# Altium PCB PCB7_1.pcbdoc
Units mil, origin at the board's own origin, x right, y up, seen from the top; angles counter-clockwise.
Board outline 1240 x 2672.95 mil, 2 copper layers (Top Layer, Bottom Layer); 61 components, 30 nets, 228 pads, 88 vias.
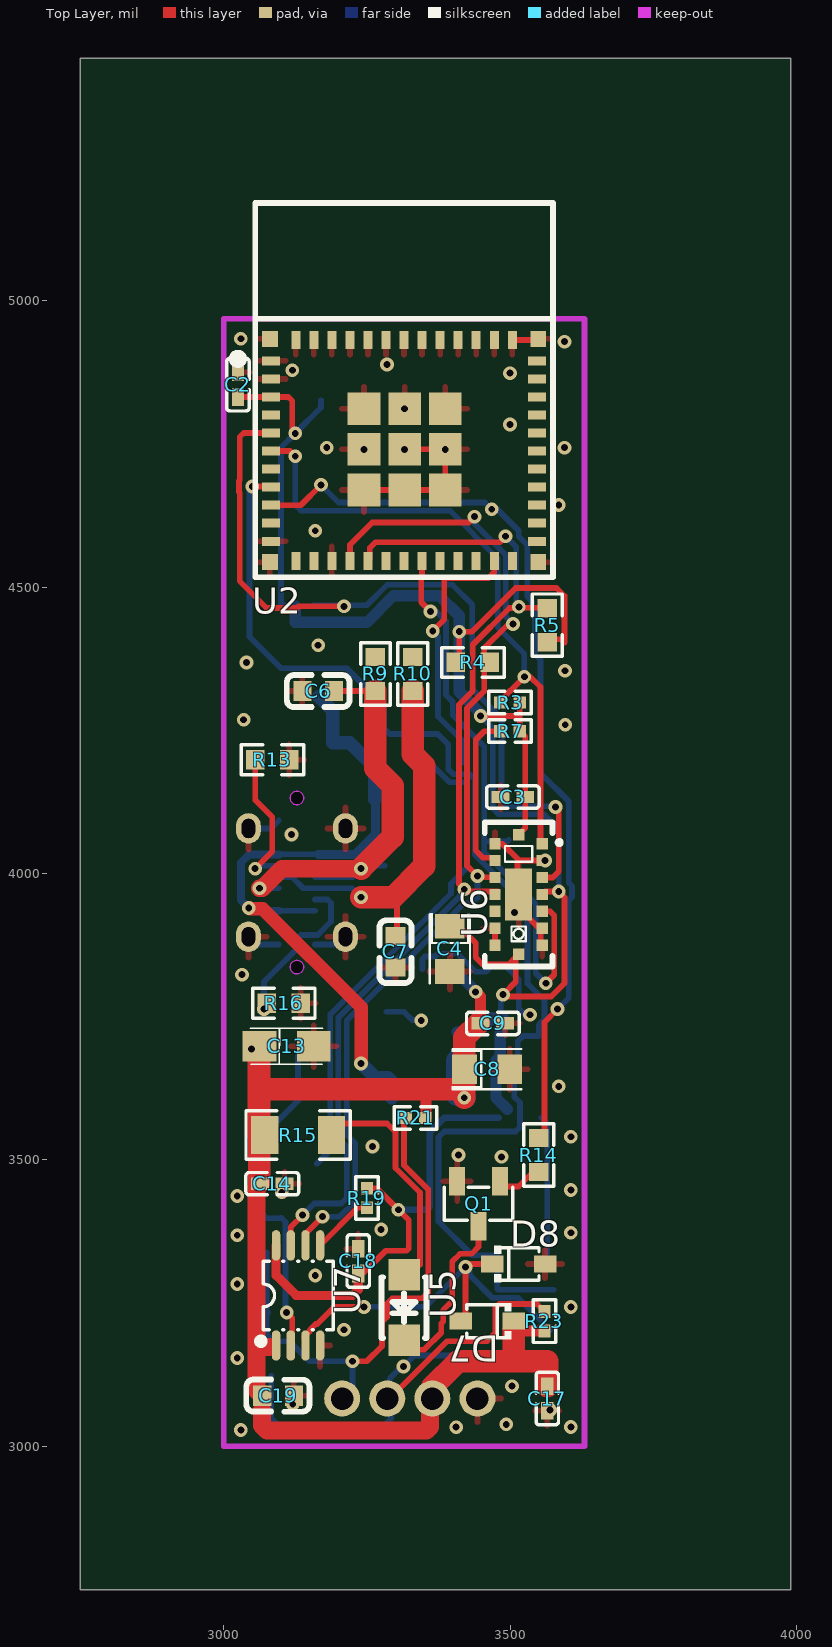
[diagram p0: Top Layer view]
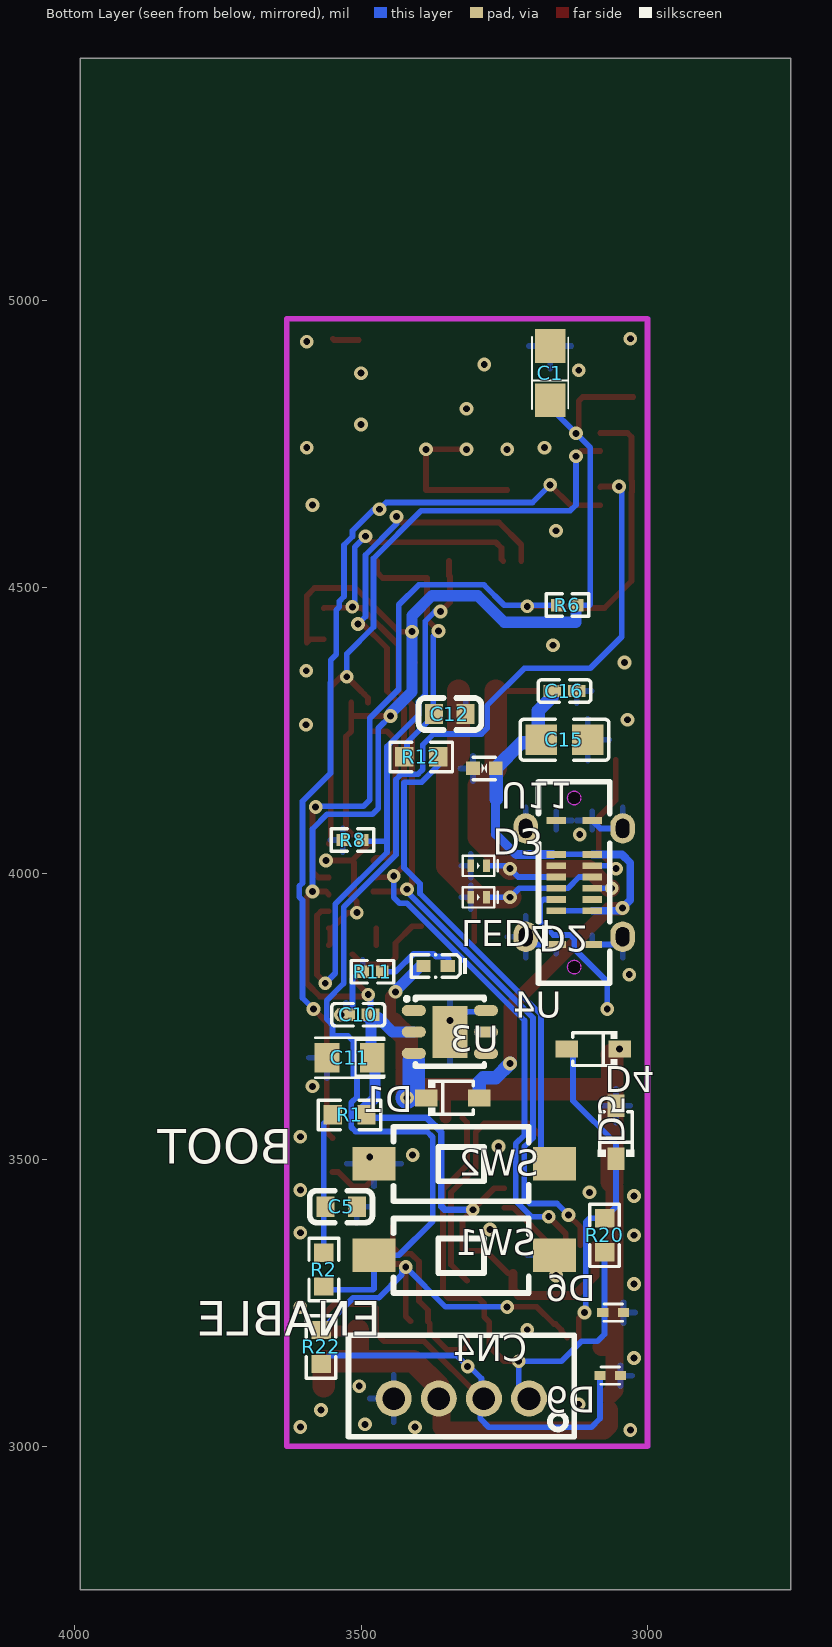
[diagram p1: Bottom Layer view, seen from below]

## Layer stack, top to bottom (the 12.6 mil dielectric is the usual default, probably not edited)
Top Layer: signal copper (thickness not stored)
Dielectric: dielectric 12.6, FR-4, Dk 4.8
Bottom Layer: signal copper (thickness not stored)

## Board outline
3990,2750 2750,2750 2750,5422.95 3990,5422.95

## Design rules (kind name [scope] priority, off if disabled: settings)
BoardOutlineClearance copperThickness1oz [All] p0: genericclearance=10 ignorepadtopadclearanceinfootprint=FALSE except(0: Arc-SplitContinuation Track-SplitContinuation SMDPad-SplitContinuation THPad-SplitContinuation Via-SplitContinuation Fill-SplitContinuation Poly-SplitContinuation Region-SplitContinuation Text-SplitContinuation; 6: Track-CutoutEdge SMDPad-CutoutEdge THPad-CutoutEdge Via-CutoutEdge Region-CutoutEdge; 11.8: Track-OutlineEdge SMDPad-OutlineEdge THPad-OutlineEdge Via-OutlineEdge Fill-OutlineEdge Region-OutlineEdge Poly-OutlineEdge Text-OutlineEdge Fill-CutoutEdge)
BoardOutlineClearance copperThickness2oz [All] p0: genericclearance=10 ignorepadtopadclearanceinfootprint=FALSE except(0: Arc-SplitContinuation Track-SplitContinuation SMDPad-SplitContinuation THPad-SplitContinuation Via-SplitContinuation Fill-SplitContinuation Poly-SplitContinuation Region-SplitContinuation Text-SplitContinuation; 6: Track-CutoutEdge SMDPad-CutoutEdge THPad-CutoutEdge Via-CutoutEdge Region-CutoutEdge; 11.8: Track-OutlineEdge SMDPad-OutlineEdge THPad-OutlineEdge Via-OutlineEdge Fill-OutlineEdge Region-OutlineEdge Poly-OutlineEdge Text-OutlineEdge Fill-CutoutEdge)
Clearance copperThickness1oz [(InNet('VDD33') OR InNet('GND') OR InNet('$3N26046') OR InNet('GPIO12_USB_DN') OR InNet('GPIO13_USB_DP') OR InNet('+5V_USB') OR InNet('$3N7934') OR InNet('$3N11377') OR InNet('$3N11381') OR InNet('GPIO2') OR InNet('GPIO3') OR InNet('I2C_SDA') OR InNet('I2C_SCL') OR InNet('ENABLE') OR InNet('$3N7054') OR InNet('$3N7060') OR InNet('$3N26307') OR InNet('GPIO4') OR InNet('$3N11357') OR InNet('$3N17354') OR InNet('GPIO14') OR InNet('$3N33566') OR InNet('$4N496') OR InNet('SCL1_S5V') OR InNet('SDA1_S5V') OR InNet('VBUS') OR InNet('SCL1_A5V') OR InNet('$3N36981') OR InNet('SDA1_A5V') OR InNet('$3N35247'))] p1: gap=7 ignorepadtopadclearanceinfootprint=FALSE except(4: Track-Track; 6: Track-SMDPad SMDPad-SMDPad Track-THPad SMDPad-THPad THPad-THPad Track-Via SMDPad-Via THPad-Via Via-Via SMDPad-Fill THPad-Fill Via-Fill Fill-Fill Track-Region SMDPad-Region THPad-Region Via-Region Region-Region Track-Poly SMDPad-Poly THPad-Poly Via-Poly Fill-Poly Region-Poly Poly-Poly Track-Text SMDPad-Text THPad-Text Via-Text Fill-Text Region-Text Poly-Text Text-Text; 6.9: Track-Hole SMDPad-Hole THPad-Hole Via-Hole Fill-Hole Region-Hole Poly-Hole Text-Hole Sheet-Hole; 11.8: Track-Fill Fill-Region Track-Sheet SMDPad-Sheet THPad-Sheet Via-Sheet Fill-Sheet Region-Sheet Poly-Sheet Text-Sheet)
Clearance copperThickness2oz [All] p1: gap=7 ignorepadtopadclearanceinfootprint=FALSE except(6: Track-SMDPad SMDPad-SMDPad Track-THPad SMDPad-THPad THPad-THPad Track-Via SMDPad-Via THPad-Via Via-Via SMDPad-Fill THPad-Fill Via-Fill Fill-Fill Track-Region SMDPad-Region THPad-Region Via-Region Region-Region Track-Poly SMDPad-Poly THPad-Poly Via-Poly Fill-Poly Region-Poly Poly-Poly Track-Text SMDPad-Text THPad-Text Via-Text Fill-Text Region-Text Poly-Text Text-Text; 6.9: Track-Hole SMDPad-Hole THPad-Hole Via-Hole Fill-Hole Region-Hole Poly-Hole Text-Hole Sheet-Hole; 8: Track-Track; 11.8: Track-Fill Fill-Region Track-Sheet SMDPad-Sheet THPad-Sheet Via-Sheet Fill-Sheet Region-Sheet Poly-Sheet Text-Sheet)
DiffPairsRouting differentialPair [All] p1: maxuncoupledlength=10 minlimit=5.9843 maxlimit=5.9843 mostfreqgap=5.9843 toplayer_minwidth=5 toplayer_prefwidth=10 toplayer_maxwidth=100 bottomlayer_minwidth=5 bottomlayer_prefwidth=10 bottomlayer_maxwidth=100
PasteMaskExpansion pasteMaskExpansion [All] p1: expansion=0
PlaneConnect innerPlane [All] p1: planeconnectstyle=Relief reliefexpansion=20 reliefentries=4 reliefconductorwidth=10 reliefairgap=10
PolygonConnect copperRegion [All] p1: connectstyle=Direct reliefentries=4 reliefconductorwidth=10 polygonreliefangle="90 Angle" airgapwidth=10
PolygonConnect USB_CR [All] p1: connectstyle=Direct reliefentries=4 reliefconductorwidth=10 polygonreliefangle="90 Angle" airgapwidth=10
PolygonConnect GND [All] p1: connectstyle=Relief reliefentries=4 reliefconductorwidth=10 polygonreliefangle="90 Angle" airgapwidth=10
RoutingVias viaSize [All] p1: viastyle="Through Hole" holewidth=12.0078 minholewidth=11.811 maxholewidth=248.0314 width=24.0158 minwidth=19.685 maxwidth=393.7008
SolderMaskExpansion solderMaskExpansion [All] p1: useseparateexpansions=TRUE expansion=2.0079 expansionbottom=2.0079
Width copperThickness1oz [All] p1: maxlimit=100 minlimit=5 preferedwidth=10
Width copperThickness2oz [All] p1: maxlimit=100 minlimit=8 preferedwidth=10

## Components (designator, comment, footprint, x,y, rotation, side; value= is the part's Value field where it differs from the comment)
C1 "" CASE-A_3216 3170,4873.5 r90 bottom
C2 "" C0402 3025,4853.5 r270 top locked
C3 "" C0402 3505,4133.5 r180 top
C4 "" CAP-SMD_L2.0-W1.3-FD 3395,3868.5 r270 top
C5 "" C0603 3535,3418.5 r180 bottom
C6 "" C0603 3165,4318.5 r180 top
C7 "" C0603 3300,3863.5 r270 top
C8 "" CAP-SMD_L2.0-W1.3-FD 3460,3658.5 r0 top
C9 "" C0402 3470,3738.5 r0 top
C10 "" C0402 3505,3753.5 r0 bottom
C11 "" CAP-SMD_L2.0-W1.3-FD 3520,3678.5 r0 bottom
C12 "" C0603 3345,4278.5 r180 bottom
C13 "" CASE-A_3216 3110,3698.5 r0 top
C14 "" C0402 3085,3458.5 r180 top
C15 "" C0805 3145,4233.5 r180 bottom
C16 "" C0402 3145,4318.5 r180 bottom
C17 "" C0402 3565,3083.5 r270 top
C18 "" C0402 3235,3323.5 r270 top
C19 "" C0603 3095,3088.5 r0 top
CN4 "" CONN-TH_B4B-PH-K-S 3325,3083.5 r180 bottom locked
D1 "" SOD-323_L1.8-W1.3-LS2.5-RD 3340,3608.5 r180 bottom
D2 "" X2SON-2_L1.0-W0.6-P0.70-RD 3295,3958.5 r0 bottom
D3 "" X2SON-2_L1.0-W0.6-P0.70-RD 3295,4013.5 r0 bottom
D4 "" SOD-323_L1.8-W1.3-LS2.5-RD 3095,3693.5 r0 bottom
D5 "" SOD-323_L1.8-W1.3-LS2.5-RD 3055,3548.5 r90 bottom
D6 "" SOD-923_L0.8-W0.6-LS1.0-BI 3060,3233.5 r180 bottom
D7 "" SOD-323_L1.8-W1.3-LS2.5-RD 3460,3218.5 r180 top
D8 "" SOD-323_L1.8-W1.3-LS2.5-RD 3515,3318.5 r0 top
D9 "" SOD-923_L0.8-W0.6-LS1.0-BI 3065,3123.5 r180 bottom
LED4 "" LED0402-RD_BLUE 3370,3838.5 r0 bottom
Q1 "" SOT-23-3_L2.9-W1.3-P1.90-LS2.4-BR 3445,3423.5 r90 top
R1 "" R0603 3520,3578.5 r180 bottom
R2 "" R0603 3565,3308.5 r270 bottom
R3 "" R0402 3500,4298.5 r0 top
R4 "" R0603 3435,4368.5 r180 top
R5 "" R0603 3565,4433.5 r270 top
R6 "" R0402 3140,4468.5 r180 bottom
R7 "" R0402 3500,4248.5 r0 top
R8 "" R0402 3515,4058.5 r180 bottom
R9 "" R0603 3265,4348.5 r90 top
R10 "" R0603 3330,4348.5 r90 top
R11 "" R0402 3480,3828.5 r0 bottom
R12 "" R0603 3395,4203.5 r0 bottom
R13 "" R0603 3085,4198.5 r0 top
R14 "" R0603 3550,3508.5 r270 top
R15 "" R1206 3130,3543.5 r0 top
R16 "" R0603 3105,3773.5 r0 top
R19 "" R0402 3250,3433.5 r270 top
R20 "" R0603 3075,3368.5 r270 bottom
R21 "" R0402 3335,3573.5 r0 top
R22 "" R0603 3570,3173.5 r270 bottom
R23 "" R0402 3560,3218.5 r270 top
SW1 "" SW-SMD_L6.0-W3.3-LS8.0 3320,3333.5 r180 bottom locked
SW2 "" SW-SMD_L6.0-W3.3-LS8.0 3320,3493.5 r180 bottom locked
U2 "" WIFIM-SMD_61P-L16.6-W13.2-P0.80-ESP32-C6-MINI-1-N4 3314.96,4738.5 r0 top locked
U3 "" DFN-6_L3.0-W3.0-P0.95-BL-EP-1 3345,3723.5 r270 bottom
U4 "" TYPE-C-SMD_USB4120-03-C 3127.95,3984.25 r90 bottom locked
U5 "" LED-SMD_L3.0-W2.0-R-RD 3314.96,3242.17 r90 top
U6 "" LGA-16_L6.4-W3.0_VL53L5CXV0GC-1 3515,3963.5 r90 top
U7 "" TSSOP-8_L3.0-W3.0-P0.65-LS4.9-BL 3130,3263.5 r0 top
U11 "" X1SON-2_L1.0-W0.6-P0.65-BI 3285,4183.5 r0 bottom

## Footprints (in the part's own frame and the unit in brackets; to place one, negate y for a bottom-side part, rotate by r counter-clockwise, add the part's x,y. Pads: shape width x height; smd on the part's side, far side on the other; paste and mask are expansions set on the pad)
C0402 [mm]
  rect 0.79x0.54 smd: 1(-0.545,0) 2(0.545,0)
  silkscreen extent -1.17,-0.5 1.17,0.5
C0603 [mm]
  rect 0.8x0.9 smd: 1(-0.7,0) 2(0.7,0)
  silkscreen extent -1.39,-0.71 1.39,0.71
C0805 [mm]
  rect 1.41x1.35 smd: 1(-1.03,0) 2(1.03,0)
  silkscreen extent -1.96,-0.9 1.96,0.9
CAP-SMD_L2.0-W1.3-FD [mm]
  rect 1.1x1.3 smd: 1(-1,0) 2(1,0)
  silkscreen extent -1.57,-0.89 1.52,0.89
CASE-A_3216 [mil]
  rect 59.05x53.5 smd: 1(-47.24,0) 2(47.24,0)
  silkscreen extent -63,-32 63,32
CONN-TH_B4B-PH-K-S [mm]
  round 1.6 hole 1: 1(3,0) 2(1,0) 3(-1,0) 4(-3,0)
  silkscreen extent -5,-1.7 5,2.8
DFN-6_L3.0-W3.0-P0.95-BL-EP-1 [mm]
  oval 0.49x1.07 smd: 1(-0.95,-1.6) 2(0,-1.6) 3(0.95,-1.6) 4(0.95,1.6) 5(0,1.6) 6(-0.95,1.6)
  rect 2.3x1.55 smd: 7(0,0)
  silkscreen extent -1.56,-2 1.52,1.52
LED0402-RD_BLUE [mm]
  rect 0.636x0.54 smd: 1(-0.538,0) 2(0.538,0)
  silkscreen extent -1.39,-0.54 1.09,0.54
LED-SMD_L3.0-W2.0-R-RD [mm]
  rect 1.4x1.4 smd: 1(1.45,0) 2(-1.45,0)
  silkscreen extent -1.35,-1 1.35,1
LGA-16_L6.4-W3.0_VL53L5CXV0GC-1 [mm]
  rect 0.5x0.5 smd: A1(2.25,-1.05) A2(1.5,-1.05) A3(0.75,-1.05) A4(0,-1.05) A5(-0.75,-1.05) A6(-1.5,-1.05) A7(-2.25,-1.05) B1(2.65,0) B7(-2.65,0) C1(2.25,1.05) C2(1.5,1.05) C3(0.75,1.05) C4(0,1.05) C5(-0.75,1.05) C6(-1.5,1.05) C7(-2.25,1.05)
  rect 2.316x1.2 smd: B4(0,0)
  silkscreen extent -3.2,-1.9 3.2,1.5
R0402 [mm]
  rect 0.566x0.54 smd: 1(-0.433,0) 2(0.433,0)
  silkscreen extent -0.94,-0.5 0.94,0.5
R0603 [mil]
  rect 31.75x34.02 smd: 1(-29.66,0) 2(29.66,0)
  silkscreen extent -55,-26 55,26
R1206 [mil]
  rect 47.54x66.97 smd: 1(-58.22,0) 2(58.22,0)
  silkscreen extent -91,-42 91,42
SOD-323_L1.8-W1.3-LS2.5-RD [mm]
  rect 1x0.75 smd: 1(-1.173,0) 2(1.173,0)
  silkscreen extent -1.08,-0.8 0.9,0.8
SOD-923_L0.8-W0.6-LS1.0-BI [mm]
  rect 0.5x0.4 smd: 1(-0.457,0) 2(0.457,0)
  silkscreen extent -0.41,-0.38 0.41,0.38
SOT-23-3_L2.9-W1.3-P1.90-LS2.4-BR [mm]
  rect 1.25x0.7 smd: 1(1,-0.95) 2(1,0.95) 3(-1,0)
  silkscreen extent -0.73,-1.53 0.73,1.53
SW-SMD_L6.0-W3.3-LS8.0 [mm]
  rect 1.9x1.5 smd: 1(-4,0) 2(4,0)
  silkscreen extent -3.14,-1.67 2.86,1.63
TSSOP-8_L3.0-W3.0-P0.65-LS4.9-BL [mm]
  oval 0.37x1.35 smd: 1(-0.975,-2.22) 2(-0.325,-2.22) 3(0.325,-2.22) 4(0.975,-2.22) 5(0.975,2.22) 6(0.325,2.22) 7(-0.325,2.22) 8(-0.975,2.22)
  silkscreen extent -1.8,-2.18 1.55,1.52
TYPE-C-SMD_USB4120-03-C [mm]
  oval 1.35x1.1 hole 0.6 slot 0.85 at 0 deg: 0(-2.4,-2.15) 0(-2.4,2.15) 0(2.4,-2.15) 0(2.4,2.15)
  rect 0.3x0.87 smd: A1(-2.75,0.8) A4(-1.25,0.8) A5(-0.75,0.8) A6(-0.25,0.8) A7(0.25,0.8) A8(0.75,0.8) A9(1.25,0.8) A12(2.75,0.8) B1(2.75,-0.8) B4(1.25,-0.8) B5(0.75,-0.8) B6(0.25,-0.8) B7(-0.25,-0.8) B8(-0.75,-0.8) B9(-1.25,-0.8) B12(-2.75,-0.8)
  Board Outline Layer circle w0.005: c-3.75,0 r0.3
  Board Outline Layer circle w0.005: c3.75,0 r0.3
  Board Outline Layer region: -3.75,0.3 -3.88,0.27 -3.985,0.187 -4.043,0.067 -4.043,-0.067 -3.985,-0.187 -3.88,-0.27 -3.75,-0.3 -3.75,-0.3 -3.62,-0.27 -3.516,-0.187 -3.458,-0.067 -3.458,0.067 -3.516,0.187 -3.62,0.27 -3.75,0.3
  Board Outline Layer region: 3.75,0.3 3.62,0.27 3.516,0.187 3.458,0.067 3.458,-0.067 3.516,-0.187 3.62,-0.27 3.75,-0.3 3.75,-0.3 3.88,-0.27 3.985,-0.187 4.043,-0.067 4.043,0.067 3.985,0.187 3.88,0.27 3.75,0.3
  Multi-Layer board cut-out: -3.75,0.3 -3.88,0.27 -3.985,0.187 -4.043,0.067 -4.043,-0.067 -3.985,-0.187 -3.88,-0.27 -3.75,-0.3 -3.75,-0.3 -3.62,-0.27 -3.516,-0.187 -3.458,-0.067 -3.458,0.067 -3.516,0.187 -3.62,0.27 -3.75,0.3
  Multi-Layer board cut-out: 3.75,0.3 3.62,0.27 3.516,0.187 3.458,0.067 3.458,-0.067 3.516,-0.187 3.62,-0.27 3.75,-0.3 3.75,-0.3 3.88,-0.27 3.985,-0.187 4.043,-0.067 4.043,0.067 3.985,0.187 3.88,0.27 3.75,0.3
  silkscreen extent -4.47,-1.58 4.47,1.58
WIFIM-SMD_61P-L16.6-W13.2-P0.80-ESP32-C6-MINI-1-N4 [mm]
  rect 0.8x0.4 smd: 1(-5.9,3.975) 2(-5.9,3.175) 3(-5.9,2.375) 4(-5.9,1.575) 5(-5.9,0.775) 6(-5.9,-0.025) 7(-5.9,-0.825) 8(-5.9,-1.625) 9(-5.9,-2.425) 10(-5.9,-3.225) 11(-5.9,-4.025) 25(5.9,-4.025) 26(5.9,-3.225) 27(5.9,-2.425) 28(5.9,-1.625) 29(5.9,-0.825) 30(5.9,-0.025) 31(5.9,0.775) 32(5.9,1.575) 33(5.9,2.375) 34(5.9,3.175) 35(5.9,3.975)
  rect 0.4x0.8 smd: 12(-4.8,-4.9) 13(-4,-4.9) 14(-3.2,-4.9) 15(-2.4,-4.9) 16(-1.6,-4.9) 17(-0.8,-4.9) 18(0,-4.9) 19(0.8,-4.9) 20(1.6,-4.9) 21(2.4,-4.9) 22(3.2,-4.9) 23(4,-4.9) 24(4.8,-4.9) 36(4.8,4.9) 37(4,4.9) 38(3.2,4.9) 39(2.4,4.9) 40(1.6,4.9) 41(0.8,4.9) 42(0,4.9) 43(-0.8,4.9) 44(-1.6,4.9) 45(-2.4,4.9) 46(-3.2,4.9) 47(-4,4.9) 48(-4.8,4.9)
  rect 1.45x1.45 smd: 49(-1.775,-1.75) 49(-1.775,0.05) 49(-1.775,1.85) 49(0.025,-1.75) 49(0.025,0.05) 49(0.025,1.85) 49(1.825,-1.75) 49(1.825,0.05) 49(1.825,1.85)
  rect 0.7x0.7 smd: 50(5.95,4.95) 51(5.95,-4.95) 52(-5.95,-4.95) 53(-5.95,4.95)
  silkscreen extent -7.57,-5.62 6.6,10.98
X1SON-2_L1.0-W0.6-P0.65-BI [mm]
  rect 0.6x0.6 smd: 1(-0.5,0) 2(0.5,0)
  silkscreen extent -0.5,-0.5 0.5,0.5
X2SON-2_L1.0-W0.6-P0.70-RD [mm]
  rect 0.3x0.55 smd: 1(-0.35,0) 2(0.35,0)
  silkscreen extent -0.85,-0.45 0.7,0.45

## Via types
v1: diameter 24.02, hole 12.01, Top Layer to Bottom Layer, 88 vias

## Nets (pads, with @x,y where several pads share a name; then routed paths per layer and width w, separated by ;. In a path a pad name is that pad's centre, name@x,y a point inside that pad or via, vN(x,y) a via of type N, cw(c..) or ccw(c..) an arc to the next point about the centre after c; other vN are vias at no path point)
$3N7054: R9.2 U2.17
$3N7060: R10.2 U2.18
$3N7934: C12.1 R12.2 U2.23 | length 464.9
  Top Layer w10: v1(3365,4423.5) 3385,4443.5 3385,4515.95 3462.44,4515.95 3472.44,4525.95 U2.23
  Bottom Layer w10: v1(3365,4423.5) 3374.25,4414.25 3374.25,4274.25 3420,4228.5 3420,4193.84 R12.2@3419.66,4193.5
$3N11357: R15.2 U5.1 | length 415.1
  Top Layer w10: R15.2 3208.3,3563.58 3285,3563.58 3300,3548.58 3300,3486.02 3342.99,3443.03 3342.99,3317.29 U5.1@3314.96,3289.26
$3N11377: Q1.1 R14.2 | length 82
  Top Layer w10: Q1.1 3491.77,3453.5 3514.66,3453.5 3540,3478.84 R14.2
$3N11381: Q1.3 U5.2 | length 314.4
  Top Layer w10: U5.2 3314.96,3175.08 3321.53,3168.5 3350,3168.5 3380,3198.5 3380,3214.65 3383.17,3217.82 3383.17,3237.82 3399.09,3253.75 3399.09,3322.58 3412.56,3336.05 3432.55,3336.05 3445,3348.5 Q1.3
$3N17354: R16.1 U4.A5 | length 281.4
  Bottom Layer w10: v1(3070.34,3763.5) 3070.34,3811.24 3127.93,3868.83 3127.93,3885.8 3135,3892.87 3164.37,3892.87 3187.56,3916.06 3187.56,3948.5 3181.34,3954.72 U4.A5
$3N26046: C5.1 R1.1 R2.1 | length 239.8
  Bottom Layer w10: R1.1@3555,3573.84 3565,3563.84 R2.1
$3N26307: R12.1 SW2.2 | length 852.9
  Bottom Layer w10: SW2.2 3185.98,3516.97 3185.98,3754.13 3397.01,3965.15 3397.01,3982.19 3425,4010.18 3425,4158.5 3424.02,4159.49 3394.36,4159.49 R12.1@3360.34,4193.5
$3N33566: R7.1 U6.C2 | length 288.5
  Top Layer w10: U6.C2@3478.66,4022.56 3473.66,4027.56 3452.54,4027.56 3440,4040.11 3440,4233.5 3455,4248.5 R7.1
$3N35247: LED4.1 R11.1 | length 152
  Bottom Layer w10: LED4.1@3347.33,3833.5 3347.33,3850.84 3351.61,3855.12 3369.11,3855.12 3374.11,3860.12 3408.27,3860.12 3439.88,3828.5 3457.96,3828.5 R11.1@3462.96,3833.5
$3N36981: R13.1 U4.B5 | length 258.4
  Top Layer w10: v1(3055,4008.5) 3085,4038.5 3085,4098.5 3055.34,4128.16 R13.1
  Bottom Layer w10: v1(3055,4008.5) 3060.28,4013.78 U4.B5
$4N496: R19.2 U7.5 | length 108.8
  Top Layer w10: U7.5 3233.95,3416.46 R19.2
+5V_USB: C8.1 C9.1 C13.1 C14.2 C17.1 C19.1 CN4.3 D1.1 D4.1 D7.1 LED4.2 R15.1 R21.2 R23.2 U3.3 U7.1 | length 2070.2
  Top Layer w19.68: R21.2 3353.22,3574.68 3353.22,3603.5 ; v1(3440,3793.5) 3448.54,3784.96 C9.1 ; 3513.2,3201.46 R23.2
  Top Layer w31.5: C14.2 3057.56,3452.52 3057.56,3173.42 ; 3067.07,3063.87 3067.07,3036.43 3075.94,3027.56 3354.06,3027.56 3360,3033.5 3360,3079.13 CN4.3 ; C19.1 3057.56,3098.38 3057.56,3173.42 ; 3080,3173.42 3057.56,3173.42
  Top Layer w39.37: C14.2@3062.01,3461.97 3062.01,3543.28 3061.78,3543.5 3061.78,3623.5 ; C13.1@3062.76,3683.5 3061.78,3682.52 3061.78,3623.5 ; CN4.3 3364.37,3104.02 3408.86,3148.5 3505.52,3148.5 ; 3404.59,3623.5 3061.78,3623.5 ; v1(3420,3608.5) 3420,3652.87 C8.1@3420.63,3653.5 ; C8.1@3420,3662.87 3420,3713.5 C9.1@3445,3738.5 ; 3506.16,3202.34 3506.16,3149.15 3505.52,3148.5 ; C17.1 3565,3148.5 3505.52,3148.5
  Bottom Layer w19.68: LED4.2@3396.19,3838.5 3440,3794.69 v1(3440,3793.5)
  Bottom Layer w39.37: 3407.99,3613.5 3407.99,3673.5 ; v1(3420,3608.5) v1@3420.63,3608.5
  other v1: 3048.84,3693.5
ENABLE: R2.2 SW1.1 U2.8 | length 2114.5
  Top Layer w10: v1(3050,4675.61) 3081.58,4675.61 U2.8
  Bottom Layer w10: v1(3050,4675.61) 3045,4670.61 3045,4413.5 3100,4358.5 3215,4358.5 3280,4293.5 3280,4253.5 3290,4243.5 3373.76,4243.5 3392.2,4225.06 3392.2,4181.95 3400.64,4173.5 3429.82,4173.5 3439.02,4164.31 3439.02,4032.75 3530.49,3941.28 3530.49,3808 3560,3778.49 3560,3745.95 3553,3738.95 3553,3738.32 3550,3735.33 3550,3716.35 3522.93,3716.35 3513.27,3706.69 3513.27,3648.36 3507.21,3642.31 3507.21,3610.05 3517.2,3600.06 3517.2,3556.95 3509.77,3549.51 3385,3549.51 3375,3539.51 3375,3392.66 3434.16,3333.5 SW1.1 ; SW1.1@3477.48,3324.15 3477.48,3275.26 3479.24,3273.5 R2.2@3576.5,3273.5
GND: C1.2 C2.1 C3.2 C4.2 C5.2 C6.2 C7.2 C8.2 C9.2 C10.2 C11.2 C12.2 C13.2 C14.1 C15.2 C16.2 C17.2 C18.1 C19.2 CN4.4 D2.2 D3.2 D5.2 D6.2 D8.2 D9.2 Q1.2 R8.1 R11.2 R13.2 R16.2 SW1.2 SW2.1 U2.1 U2.2 U2.11 U2.14 U2.36 U2.37 U2.38 U2.39 U2.40 U2.41 U2.42 U2.43 U2.44 U2.45 U2.46 U2.47 U2.48 U2.49 U2.50 U2.51 U2.52 U2.53 U3.6 U3.7 U4.0 U4.A1 U4.A12 U4.B1 U4.B12 U6.A2 U6.A6 U6.A7 U6.B4 U6.C1 U6.C6 U6.C7 U7.4 U11.2 | length 982.7
  Top Layer w10: U2.49@3245.07,4669.61 3315.94,4669.61 3386.8,4669.61 v1(3386.8,4740.47) v1(3315.94,4740.47) ; U6.C7 U6.C6 ; U6.C1@3478.66,4052.08 3486.42,4052.08 3515.94,4022.56 ; U2.36 3547.24,4931.41 U2.50 ; U6.B4@3519.99,3963.5 U6.B4@3512.49,3956 ; U6.A6@3553.84,3901.95 3553.84,3877.42 U6.A7 ; U6.A6 3550.64,3904.45 3523.34,3931.75 v1(3507.49,3931.75) 3507.49,3951 U6.B4@3512.49,3956 ; v1(3561.34,4022.56) 3515.94,4022.56 ; U6.B4@3512.49,3956 3512.49,4019.12 3515.94,4022.56
  Bottom Layer w10: U4.0@3043.31,3889.76 3057.09,3875.98 U4.B12 ; U4.0@3043.31,4078.74 3082.68,4078.74 U4.B1 ; U4.A1 3198.82,3875.98 U4.0@3212.6,3889.76 ; U3.6@3284.4,3758.5 3315,3758.5 3329.37,3744.13 3344.37,3744.13 v1(3345,3743.5) ; R11.2@3497.04,3833.5 3515,3815.54 3515,3764.96 C10.2
  other v1: 3030,3028.5 3405.92,3033.5 3606.1,3033.69 3493.42,3038.5 3570,3063.5 3120.59,3073.5 3503.19,3105.16 3023.82,3154.29 3210,3203.5 3606.1,3243.5 3023.82,3283.5 3160,3298.5 3023.82,3368.5 3606.1,3372.84 3275,3378.5 3023.82,3437.01 3101.46,3443.5 3606.1,3447.51 3485,3505.47 3410,3508.5 3260,3523.5 3606.1,3540.6 3585,3628.5 3535.04,3753.5 3032.01,3823.5 3118.36,4068.19 3596.32,4259.7 3035,4268.5 3595.72,4353.94 3040,4368.5 3165,4398.5 3160,4598.5 3585,4643.5 3245.07,4740.47 3180,4743.5 3595,4743.5 3500,4784 3315.94,4811.34 3500,4873.5 3120,4878.5 3285,4888.5 3595,4928.5 3030,4933.5
GPIO2: R6.1 U2.5 U6.A3 | length 1429.7
  Top Layer w10: U2.5 3035,4769.01 3027.93,4761.94 3027.93,4686.06 3027.01,4685.14 3027.01,4666.09 3027.93,4665.17 3027.93,4510.57 3075,4463.5 3127.96,4463.5 3130.92,4466.46 v1(3210,4466.46) ; U6.A3 3574.53,3993.03 3585,4003.5 3585,4110.35 v1(3579.36,4115.99)
  Bottom Layer w10: R6.1 3207.96,4468.5 v1(3210,4466.46) 3212.04,4468.5 3250,4468.5 3285.45,4503.95 3399.55,4503.95 3434.25,4469.25 3434.25,4321.77 3485,4271.02 3485,4128.5 3495.98,4117.52 3577.83,4117.52 v1(3579.36,4115.99)
GPIO3: R3.1 U2.6 U6.A1 | length 1119.8
  Top Layer w10: U2.6 3115.98,4737.52 v1(3125,4728.5) ; R3.1@3487.96,4298.5 3487.96,4306.46 3494.92,4313.42 3494.92,4313.68 3501.36,4320.12 3501.61,4320.12 v1(3525,4343.5) 3535,4343.5 3553,4325.51 3553,4055.42 U6.A1
  Bottom Layer w10: v1(3125,4728.5) 3125,4643.5 3135,4633.5 3395,4633.5 3478.33,4550.17 3478.33,4430.17 3525,4383.5 v1(3525,4343.5)
GPIO4: R14.1 U2.9 | length 1603.1
  Top Layer w10: U2.9 3134.53,4643.03 v1(3170,4678.5) ; R14.1 3560,3548.16 3560,3740.51 v1(3582.99,3763.5)
  Bottom Layer w10: v1(3170,4678.5) 3200.75,4647.75 3456.24,4647.75 v1(3467.99,4636) 3477.53,4636 3515.19,4598.35 3515.19,4588.35 3530,4573.54 3530,4483.47 3538.33,4475.14 3538.33,4465.14 3543.33,4460.14 3543.33,4382.48 3552.99,4372.82 3552.99,4333.84 3553.33,4333.5 3553.33,4175.17 3602.35,4126.15 3602.35,3983.67 3607.99,3978.03 3607.99,3958.98 3602.35,3953.34 3602.35,3782.86 v1(3582.99,3763.5)
GPIO12_USB_DN: C6.1 D3.1 R9.1 U4.A7 U4.B7 | length 773.2
  Top Layer w10: C6.1 3264.66,4318.5 R9.1
  Top Layer w30: v1(3062.66,3974.41) 3067.57,3974.41 3101.66,4008.5 v1(3240,4008.5)
  Top Layer w39.37: v1(3240,4008.5) 3295,4063.5 3295,4153.5 3265,4183.5 R9.1
  Bottom Layer w10: v1(3062.66,3974.41) U4.B7 ; U4.A7 3225.59,3994.09 v1(3240,4008.5) 3245,4013.5 D3.1
GPIO13_USB_DP: C7.1 D2.1 R10.1 U4.A6 U4.B6 | length 721.6
  Top Layer w10: 3295.68,3958.5 3302.56,3951.62 C7.1@3302.56,3880.94
  Top Layer w39.37: v1(3240,3958.5) 3295.68,3958.5 3350,4012.83 3350,4188.5 3330,4208.5 R10.1
  Bottom Layer w10: U4.B6 3119.41,3994.09 3139.09,3974.41 U4.A6 3224.09,3974.41 v1(3240,3958.5) 3240.14,3958.65 D2.1@3276.08,3958.65
GPIO14: R8.2 U2.19 U6.A5 | length 1022.1
  Top Layer w10: U2.19 3346.45,4519.96 3345,4518.5 3345,4473.58 v1(3361.32,4457.26) ; U6.A5 3570.09,3933.97 3577.16,3926.9 3577.16,3823.17 v1(3562.5,3808.5)
  Bottom Layer w10: v1(3361.32,4457.26) 3371.24,4457.26 3388.27,4440.24 3388.27,4311.8 3400,4300.06 3400,4276.58 3455,4221.58 3455,4059.98 ; 3455,4057.02 3455,4036.58 3545,3946.58 3545,3826 v1(3562.5,3808.5) ; 3455.52,4056.5 3495.96,4056.5 R8.2
I2C_SCL: R5.1 U2.16 U6.C4 U7.7 | length 1849.2
  Top Layer w10: U7.7 3117.21,3382.7 3137.77,3403.25 v1(3137.77,3403.7) ; U2.16 3255,4548.63 3255,4568.5 3265,4578.5 3481.88,4578.5 v1(3492.2,4588.82) ; U6.C4@3478.66,3968.5 3424.05,3968.5 v1(3420,3972.55) 3410.98,3981.57 3410.98,4294.49 3435,4318.5 3435,4399.41 3499.09,4463.5 3513.23,4463.5 v1(3515.34,4465.61) 3517.02,4463.93 3564.24,4463.93 R5.1
  Bottom Layer w10: v1(3137.77,3403.7) 3158.07,3424 3205.49,3424 3215,3433.5 3215,3523.5 3200,3538.5 3200,3748.33 3420,3968.33 v1(3420,3972.55) ; v1(3492.2,4588.82) 3510.98,4570.04 3510.98,4469.97 v1(3515.34,4465.61)
I2C_SDA: R4.1 U2.15 U6.C3 U7.6 | length 1805.6
  Top Layer w10: U7.6 3142.8,3371.3 v1(3172.5,3401) ; U2.15 3220.47,4573.98 3259.47,4612.98 3428.04,4612.98 v1(3438.04,4622.98) ; U6.C3 3473.2,3993.5 3445.14,3993.5 v1(3442.99,3995.66) 3425,4013.65 3425,4288.5 3455,4318.5 3455,4393.5 3497.16,4435.67 v1(3505.35,4435.67)
  Bottom Layer w10: v1(3172.5,3401) 3202.5,3401 3230,3428.5 3230,3528.5 3214.96,3543.55 3214.96,3743.46 3419.7,3948.21 3432.99,3948.21 3442.99,3958.21 v1(3442.99,3995.66) ; v1(3438.04,4622.98) 3438.04,4610.46 3492.35,4556.16 3492.35,4448.67 v1(3505.35,4435.67)
SCL1_A5V: CN4.1 D6.1 R20.2 R21.1 | length 933.5
  Top Layer w10: v1(3225,3148.5) 3250,3148.5 3276.42,3174.92 3276.42,3217.18 3285,3225.77 3285,3248.97 3294.54,3258.5 3347.01,3258.5 3357.01,3268.5 3357.01,3448.83 3315,3490.84 3315,3565.54 R21.1@3322.96,3573.5
  Bottom Layer w10: R20.2 3075,3236.5 D6.1 3075,3230.5 3075,3195.65 3087.14,3183.5 3115,3183.5 3150,3148.5 v1(3225,3148.5) 3225,3101.61 CN4.1
SCL1_S5V: D4.2 D5.1 R20.1 U7.2 | length 593.4
  Top Layer w10: v1(3110,3233.5) 3120,3223.5 U7.2@3120,3178.3
  Bottom Layer w10: v1(3110,3233.5) 3107.93,3235.57 3107.93,3391.43 3100.86,3398.5 3100,3398.5 3099.66,3398.16 R20.1 3055,3418.16 D5.1 3055,3528.5 3130,3603.5 3130,3682.34 D4.2
SDA1_A5V: CN4.2 D9.1 R22.2 R23.1 | length 1047.3
  Top Layer w10: CN4.2 3290,3083.5 3390,3183.5 3460,3183.5 3474.14,3197.65 3474.14,3241.43 3481.21,3248.5 3547.04,3248.5 R23.1
  Bottom Layer w10: D9.1 3083,3048.5 3098,3033.5 3277.07,3033.5 3292.07,3048.5 3292.07,3077.06 CN4.2 3285.63,3099.13 3290,3103.5 3290,3118.5 3311.02,3139.52 v1(3314,3139.52) 3332.98,3158.5 3555.34,3158.5 R22.2
SDA1_S5V: D7.2 D8.1 R22.1 U7.3 | length 678.8
  Top Layer w10: U7.3@3140,3190.24 3150.12,3200.36 3150.12,3202.95 3160.82,3213.65 3163.42,3213.65 3193.27,3243.5 v1(3245,3243.5) ; D7.2 3422.09,3226.76 v1(3422.09,3313.06) 3427.53,3318.5 D8.1
  Bottom Layer w10: v1(3245,3243.5) 3352.53,3243.5 v1(3422.09,3313.06) 3429.09,3306.05 3429.09,3299.43 3469.03,3259.49 3513.68,3259.49 R22.1
VBUS: C15.1 C16.1 D1.2 U4.A4 U4.A9 U4.B4 U4.B9 U11.1 | length 1208.7
  Top Layer w23.62: v1(3043.82,3940) 3045.32,3938.5 3067.93,3938.5 3240,3766.43 v1(3240,3668.5)
  Bottom Layer w10: U4.B9 U4.A4 ; U4.B4 U4.A9
  Bottom Layer w13.78: U4.B9 3048.78,3935.04 v1(3043.82,3940) 3030.12,3953.7 3030.12,4018.81 3044.69,4033.39 3096.38,4033.39 U4.B4
  Bottom Layer w15.75: U4.A9@3165.8,4033.52 3228.43,4033.52 ; 3230.87,4034.37 3265,4068.5 3265,4128.82 3264.16,4129.66
  Bottom Layer w23.62: C16.1@3166.46,4308.5 3190.55,4284.41 3190.55,4228.5 3220.32,4228.5 U11.1 3265.32,4178.5 3264.16,4177.35 3264.16,4129.66 ; v1(3240,3668.5) 3265,3643.5 3286.76,3643.5 3293.84,3636.43 D1.2
VDD33: C1.1 C2.2 C3.1 C4.1 C10.1 C11.1 C18.2 R1.2 R3.2 R4.2 R5.2 R6.2 R7.2 R19.1 U2.3 U3.2 U6.A4 U6.B1 U6.B7 U7.8 | length 3860.7
  Top Layer w10: C2.2 U2.3@3082.63,4832.04 ; U2.3 3112.93,4832 3120,4824.93 3120,4773.5 v1(3125,4768.5) ; C18.2 3243.54,3302.04 3283,3341.51 3319.29,3341.51 3323,3345.22 3323,3395.17 v1(3305,3413.17) 3267.63,3450.54 R19.1 ; C4.1 3410.63,3907.87 3440,3878.5 3440,3853.5 3452.07,3841.43 3497.25,3841.43 U6.B7@3510,3854.18 ; R4.2 3411.26,4374.42 v1(3411.26,4422.25) 3433.74,4422.25 3510,4498.5 3581.22,4498.5 3595,4484.72 3595,4403.5 3589.66,4408.84 R5.2@3565,4408.84 ; v1(3448.64,4274.86) 3514.31,4274.86 3517.04,4272.13 ; U6.B7 U6.B7@3510,3854.18 ; U6.B1 3526.46,4079.3 C3.1 3526.46,4239.08 R7.2 3517.04,4272.13 ; R3.2 3517.04,4272.13 ; U6.A4 3561.34,3968.51 v1(3585,3968.51) 3595,3958.51 3595,3808.49 3572.02,3785.51 3490.49,3785.51 v1(3487.49,3788.5) 3510,3811.01 U6.B7@3510,3854.18
  Top Layer w15.75: U7.8 3091.61,3298.5 3126.61,3263.5 3225,3263.5 3235,3273.5 C18.2
  Bottom Layer w10: 3100,4469.48 3100,4743.5 v1(3125,4768.5) 3170,4813.5 C1.1 ; 3100.98,4468.5 R6.2 ; v1(3448.64,4274.86) 3470,4253.5 3470,4113.5 3480,4103.5 3559.33,4103.5 3585,4077.83 v1(3585,3968.51) ; C10.1 3483.54,3784.55 v1(3487.49,3788.5)
  Bottom Layer w11.81: v1(3305,3413.17) 3354.67,3413.17 3360,3418.5 3360,3548.5 3385,3573.5 R1.2@3480.34,3573.5
  Bottom Layer w19.68: R6.2 3125,4466.46 3125,4438.5 3250,4438.5 3296.59,4485.1 3376.25,4485.1 3411.26,4450.08 v1(3411.26,4422.25) 3411.26,4317.25 3448.64,4279.86 v1(3448.64,4274.86) ; U3.2 3445,3723.5 C10.1@3470,3748.5 ; C11.1@3480.66,3678.48 3475.66,3673.48 3475.66,3608.19 R1.2@3495.34,3588.5 ; C11.1@3482.66,3682.3 3482.66,3742.62 C10.1@3483.54,3743.5 ; C10.1@3483.54,3748.5 C10.1@3488.54,3748.5
pads on no net: U2.4 U2.7 U2.10 U2.12 U2.13 U2.20 U2.21 U2.22 U2.24 U2.25 U2.26 U2.27 U2.28 U2.29 U2.30 U2.31 U2.32 U2.33 U2.34 U2.35 U3.1 U3.4 U3.5 U4.A8 U4.B8 U6.C5

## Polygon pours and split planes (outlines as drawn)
GND on Bottom Layer (solid, remove dead copper, pour order 6): 3000,4968.5 3629.92,4968.5 3629.92,3000 3000,3000
GND on Top Layer (solid, remove dead copper, pour order 4): 3000,4968.5 3629.92,4968.5 3629.92,3000 3000,3000
$3N7060 on Top Layer (solid, remove dead copper, pour order 0): 3315,4358.5 3310,4363.5 3310,4473.5 3305,4478.5 3305,4563.5 3310,4568.5 3320,4568.5 3325,4563.5 3325,4503.5 3350,4478.5 3350,4363.5 3345,4358.5
$3N7054 on Top Layer (solid, remove dead copper, pour order 2): 3280,4358.5 3285,4363.5 3285,4468.5 3295,4478.5 3295,4563.5 3290,4568.5 3280,4568.5 3275,4563.5 3275,4503.5 3245,4473.5 3245,4363.5 3250,4358.5

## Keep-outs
Board Outline Layer:
  lines w10: 3000,3000 3629.92,3000 3629.92,4968.5 3000,4968.5 3000,3000

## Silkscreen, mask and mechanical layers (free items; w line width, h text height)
Bottom Silkscreen Layer:
  text "BOOT" at 3620,3493.5 h60
  text "ENABLE" at 3465,3193.5 h60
